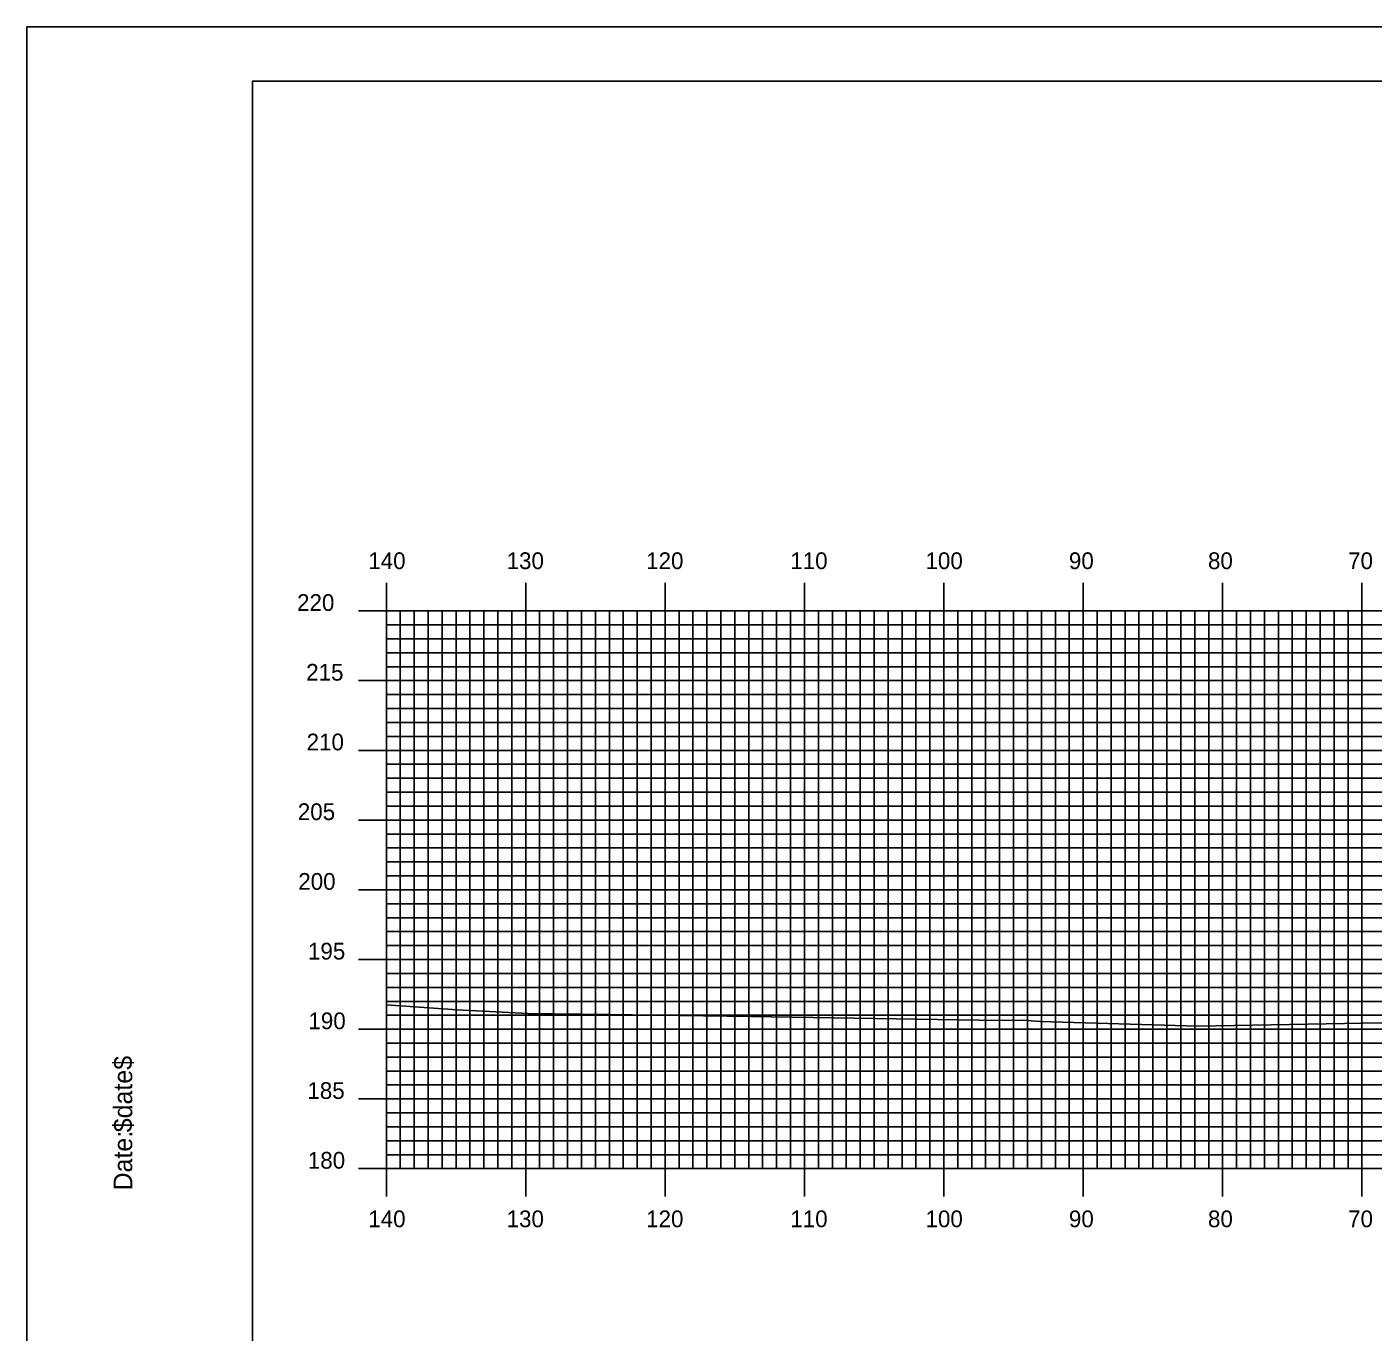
# Model space of a CAD drawing. Extents: x 1810587 to 1810930, y 442591 to 442811.
# Drawn here: x 1810586.6 to 1810683.2, y 442716.9 to 442810.5 of the extents above; entities that cross this region are included whole.
import ezdxf

# ---------------------------------------------------------------- set-up
doc = ezdxf.new("R2010")
doc.units = 0
for name, color, linetype in [('BORDER', 7, 'Continuous'), ('H_V ANNOTATION', 7, 'Continuous'), ('MAJOR', 7, 'Continuous'), ('MINOR', 7, 'Continuous'), ('PLOT BOUNDARY', 7, 'Continuous'), ('S_Roadway_Centerline', 7, 'Continuous')]:
    doc.layers.add(name, color=color, linetype=linetype)

msp = doc.modelspace()

# ---------------------------------------------------------------- linework, layer by layer
at = {"layer": 'BORDER'}
msp.add_lwpolyline([(1810602.777, 442596.665), (1810922.777, 442596.665), (1810922.777, 442806.665), (1810602.777, 442806.665)], close=True, dxfattribs=at)
at = {"layer": 'MAJOR'}
for p, q in [((1810612.377, 442770.669), (1810612.377, 442768.665)), ((1810622.377, 442770.669), (1810622.377, 442768.665)), ((1810632.377, 442770.669), (1810632.377, 442768.665)), ((1810642.377, 442770.669), (1810642.377, 442768.665)), ((1810652.377, 442770.669), (1810652.377, 442768.665)), ((1810662.377, 442770.669), (1810662.377, 442768.665)), ((1810672.377, 442770.669), (1810672.377, 442768.665)), ((1810682.377, 442770.669), (1810682.377, 442768.665)), ((1810610.373, 442768.665), (1810612.377, 442768.665)), ((1810612.377, 442768.665), (1810892.377, 442768.665)), ((1810612.377, 442728.665), (1810612.377, 442768.665)), ((1810612.377, 442728.665), (1810612.377, 442768.665)), ((1810612.377, 442768.665), (1810892.377, 442768.665)), ((1810622.377, 442728.665), (1810622.377, 442768.665)), ((1810632.377, 442728.665), (1810632.377, 442768.665)), ((1810642.377, 442728.665), (1810642.377, 442768.665)), ((1810652.377, 442728.665), (1810652.377, 442768.665)), ((1810662.377, 442728.665), (1810662.377, 442768.665)), ((1810672.377, 442728.665), (1810672.377, 442768.665)), ((1810682.377, 442728.665), (1810682.377, 442768.665)), ((1810610.373, 442763.665), (1810612.377, 442763.665)), ((1810612.377, 442763.665), (1810892.377, 442763.665)), ((1810610.373, 442758.665), (1810612.377, 442758.665)), ((1810612.377, 442758.665), (1810892.377, 442758.665)), ((1810610.373, 442753.665), (1810612.377, 442753.665)), ((1810612.377, 442753.665), (1810892.377, 442753.665)), ((1810610.373, 442748.665), (1810612.377, 442748.665)), ((1810612.377, 442748.665), (1810892.377, 442748.665)), ((1810610.373, 442743.665), (1810612.377, 442743.665)), ((1810612.377, 442743.665), (1810892.377, 442743.665)), ((1810610.373, 442738.665), (1810612.377, 442738.665)), ((1810612.377, 442738.665), (1810892.377, 442738.665)), ((1810610.373, 442733.665), (1810612.377, 442733.665)), ((1810612.377, 442733.665), (1810892.377, 442733.665)), ((1810610.373, 442728.665), (1810612.377, 442728.665)), ((1810612.377, 442728.665), (1810892.377, 442728.665)), ((1810612.377, 442728.665), (1810892.377, 442728.665)), ((1810612.377, 442726.661), (1810612.377, 442728.665)), ((1810622.377, 442726.661), (1810622.377, 442728.665)), ((1810632.377, 442726.661), (1810632.377, 442728.665)), ((1810642.377, 442726.661), (1810642.377, 442728.665)), ((1810652.377, 442726.661), (1810652.377, 442728.665)), ((1810662.377, 442726.661), (1810662.377, 442728.665)), ((1810672.377, 442726.661), (1810672.377, 442728.665)), ((1810682.377, 442726.661), (1810682.377, 442728.665))]:
    msp.add_line(p, q, dxfattribs=at)
at = {"layer": 'MINOR'}
for p, q in [((1810613.377, 442728.665), (1810613.377, 442768.665)), ((1810614.377, 442728.665), (1810614.377, 442768.665)), ((1810615.377, 442728.665), (1810615.377, 442768.665)), ((1810616.377, 442728.665), (1810616.377, 442768.665)), ((1810617.377, 442728.665), (1810617.377, 442768.665)), ((1810618.377, 442728.665), (1810618.377, 442768.665)), ((1810619.377, 442728.665), (1810619.377, 442768.665)), ((1810620.377, 442728.665), (1810620.377, 442768.665)), ((1810621.377, 442728.665), (1810621.377, 442768.665)), ((1810623.377, 442728.665), (1810623.377, 442768.665)), ((1810624.377, 442728.665), (1810624.377, 442768.665)), ((1810625.377, 442728.665), (1810625.377, 442768.665)), ((1810626.377, 442728.665), (1810626.377, 442768.665)), ((1810627.377, 442728.665), (1810627.377, 442768.665)), ((1810628.377, 442728.665), (1810628.377, 442768.665)), ((1810629.377, 442728.665), (1810629.377, 442768.665)), ((1810630.377, 442728.665), (1810630.377, 442768.665)), ((1810631.377, 442728.665), (1810631.377, 442768.665)), ((1810633.377, 442728.665), (1810633.377, 442768.665)), ((1810634.377, 442728.665), (1810634.377, 442768.665)), ((1810635.377, 442728.665), (1810635.377, 442768.665)), ((1810636.377, 442728.665), (1810636.377, 442768.665)), ((1810637.377, 442728.665), (1810637.377, 442768.665)), ((1810638.377, 442728.665), (1810638.377, 442768.665)), ((1810639.377, 442728.665), (1810639.377, 442768.665)), ((1810640.377, 442728.665), (1810640.377, 442768.665)), ((1810641.377, 442728.665), (1810641.377, 442768.665)), ((1810643.377, 442728.665), (1810643.377, 442768.665)), ((1810644.377, 442728.665), (1810644.377, 442768.665)), ((1810645.377, 442728.665), (1810645.377, 442768.665)), ((1810646.377, 442728.665), (1810646.377, 442768.665)), ((1810647.377, 442728.665), (1810647.377, 442768.665)), ((1810648.377, 442728.665), (1810648.377, 442768.665)), ((1810649.377, 442728.665), (1810649.377, 442768.665)), ((1810650.377, 442728.665), (1810650.377, 442768.665)), ((1810651.377, 442728.665), (1810651.377, 442768.665)), ((1810653.377, 442728.665), (1810653.377, 442768.665)), ((1810654.377, 442728.665), (1810654.377, 442768.665)), ((1810655.377, 442728.665), (1810655.377, 442768.665)), ((1810656.377, 442728.665), (1810656.377, 442768.665)), ((1810657.377, 442728.665), (1810657.377, 442768.665)), ((1810658.377, 442728.665), (1810658.377, 442768.665)), ((1810659.377, 442728.665), (1810659.377, 442768.665)), ((1810660.377, 442728.665), (1810660.377, 442768.665)), ((1810661.377, 442728.665), (1810661.377, 442768.665)), ((1810663.377, 442728.665), (1810663.377, 442768.665)), ((1810664.377, 442728.665), (1810664.377, 442768.665)), ((1810665.377, 442728.665), (1810665.377, 442768.665)), ((1810666.377, 442728.665), (1810666.377, 442768.665)), ((1810667.377, 442728.665), (1810667.377, 442768.665)), ((1810668.377, 442728.665), (1810668.377, 442768.665)), ((1810669.377, 442728.665), (1810669.377, 442768.665)), ((1810670.377, 442728.665), (1810670.377, 442768.665)), ((1810671.377, 442728.665), (1810671.377, 442768.665)), ((1810673.377, 442728.665), (1810673.377, 442768.665)), ((1810674.377, 442728.665), (1810674.377, 442768.665)), ((1810675.377, 442728.665), (1810675.377, 442768.665)), ((1810676.377, 442728.665), (1810676.377, 442768.665)), ((1810677.377, 442728.665), (1810677.377, 442768.665)), ((1810678.377, 442728.665), (1810678.377, 442768.665)), ((1810679.377, 442728.665), (1810679.377, 442768.665)), ((1810680.377, 442728.665), (1810680.377, 442768.665)), ((1810681.377, 442728.665), (1810681.377, 442768.665)), ((1810612.377, 442767.665), (1810892.377, 442767.665)), ((1810612.377, 442767.665), (1810614.381, 442767.665)), ((1810612.377, 442766.665), (1810892.377, 442766.665)), ((1810612.377, 442766.665), (1810614.381, 442766.665)), ((1810612.377, 442765.665), (1810892.377, 442765.665)), ((1810612.377, 442765.665), (1810614.381, 442765.665)), ((1810612.377, 442764.665), (1810892.377, 442764.665)), ((1810612.377, 442764.665), (1810614.381, 442764.665)), ((1810612.377, 442762.665), (1810892.377, 442762.665)), ((1810612.377, 442762.665), (1810614.381, 442762.665)), ((1810612.377, 442761.665), (1810892.377, 442761.665)), ((1810612.377, 442761.665), (1810614.381, 442761.665)), ((1810612.377, 442760.665), (1810892.377, 442760.665)), ((1810612.377, 442760.665), (1810614.381, 442760.665)), ((1810612.377, 442759.665), (1810892.377, 442759.665)), ((1810612.377, 442759.665), (1810614.381, 442759.665)), ((1810612.377, 442757.665), (1810892.377, 442757.665)), ((1810612.377, 442757.665), (1810614.381, 442757.665)), ((1810612.377, 442756.665), (1810892.377, 442756.665)), ((1810612.377, 442756.665), (1810614.381, 442756.665)), ((1810612.377, 442755.665), (1810892.377, 442755.665)), ((1810612.377, 442755.665), (1810614.381, 442755.665)), ((1810612.377, 442754.665), (1810892.377, 442754.665)), ((1810612.377, 442754.665), (1810614.381, 442754.665)), ((1810612.377, 442752.665), (1810892.377, 442752.665)), ((1810612.377, 442752.665), (1810614.381, 442752.665)), ((1810612.377, 442751.665), (1810892.377, 442751.665)), ((1810612.377, 442751.665), (1810614.381, 442751.665)), ((1810612.377, 442750.665), (1810892.377, 442750.665)), ((1810612.377, 442750.665), (1810614.381, 442750.665)), ((1810612.377, 442749.665), (1810892.377, 442749.665)), ((1810612.377, 442749.665), (1810614.381, 442749.665)), ((1810612.377, 442747.665), (1810892.377, 442747.665)), ((1810612.377, 442747.665), (1810614.381, 442747.665)), ((1810612.377, 442746.665), (1810892.377, 442746.665)), ((1810612.377, 442746.665), (1810614.381, 442746.665)), ((1810612.377, 442745.665), (1810892.377, 442745.665)), ((1810612.377, 442745.665), (1810614.381, 442745.665)), ((1810612.377, 442744.665), (1810892.377, 442744.665)), ((1810612.377, 442744.665), (1810614.381, 442744.665)), ((1810612.377, 442742.665), (1810892.377, 442742.665)), ((1810612.377, 442742.665), (1810614.381, 442742.665)), ((1810612.377, 442741.665), (1810892.377, 442741.665)), ((1810612.377, 442741.665), (1810614.381, 442741.665)), ((1810612.377, 442740.665), (1810892.377, 442740.665)), ((1810612.377, 442740.665), (1810614.381, 442740.665)), ((1810612.377, 442739.665), (1810892.377, 442739.665)), ((1810612.377, 442739.665), (1810614.381, 442739.665)), ((1810612.377, 442737.665), (1810892.377, 442737.665)), ((1810612.377, 442737.665), (1810614.381, 442737.665)), ((1810612.377, 442736.665), (1810892.377, 442736.665)), ((1810612.377, 442736.665), (1810614.381, 442736.665)), ((1810612.377, 442735.665), (1810892.377, 442735.665)), ((1810612.377, 442735.665), (1810614.381, 442735.665)), ((1810612.377, 442734.665), (1810892.377, 442734.665)), ((1810612.377, 442734.665), (1810614.381, 442734.665)), ((1810612.377, 442732.665), (1810892.377, 442732.665)), ((1810612.377, 442732.665), (1810614.381, 442732.665)), ((1810612.377, 442731.665), (1810892.377, 442731.665)), ((1810612.377, 442731.665), (1810614.381, 442731.665)), ((1810612.377, 442730.665), (1810892.377, 442730.665)), ((1810612.377, 442730.665), (1810614.381, 442730.665)), ((1810612.377, 442729.665), (1810892.377, 442729.665)), ((1810612.377, 442729.665), (1810614.381, 442729.665))]:
    msp.add_line(p, q, dxfattribs=at)
at = {"layer": 'PLOT BOUNDARY'}
msp.add_lwpolyline([(1810586.59, 442590.547), (1810926.59, 442590.547), (1810926.59, 442810.547), (1810586.59, 442810.547)], close=True, dxfattribs=at)
at = {"layer": 'S_Roadway_Centerline'}
msp.add_lwpolyline([(1810612.377, 442740.403), (1810617.462, 442740.055), (1810622.558, 442739.785), (1810628.316, 442739.724), (1810638.526, 442739.577), (1810656.386, 442739.297), (1810658.007, 442739.312), (1810659.285, 442739.228), (1810670.597, 442738.88), (1810683.757, 442739.125), (1810700.479, 442738.664), (1810710.156, 442738.284), (1810720.854, 442738.411), (1810737.474, 442738.884), (1810739.437, 442738.87), (1810741.277, 442738.823), (1810752.122, 442738.14), (1810762.757, 442738.223), (1810764.361, 442738.195), (1810782.794, 442738.075)], dxfattribs=at)

# ---------------------------------------------------------------- texts
at = {"layer": 'BORDER'}
for s, p in [('$date$', (1810594.146, 442731.275)), ('Date:', (1810594.146, 442727.099))]:
    msp.add_text(s, height=1.3392, rotation=90, dxfattribs=at).set_placement(p)
at = {"layer": 'H_V ANNOTATION'}
for s, p in [('140', (1810611.081, 442771.665)), ('130', (1810621.006, 442771.665)), ('120', (1810631.017, 442771.665)), ('110', (1810641.36, 442771.665)), ('100', (1810651.06, 442771.665)), ('90', (1810661.349, 442771.665)), ('80', (1810671.327, 442771.665)), ('70', (1810681.381, 442771.665)), ('220', (1810605.972, 442768.665)), ('215', (1810606.626, 442763.665)), ('210', (1810606.658, 442758.665)), ('205', (1810606.026, 442753.665)), ('200', (1810606.058, 442748.665)), ('195', (1810606.754, 442743.665)), ('190', (1810606.786, 442738.665)), ('185', (1810606.711, 442733.665)), ('180', (1810606.743, 442728.665)), ('140', (1810611.081, 442724.465)), ('130', (1810621.006, 442724.465)), ('120', (1810631.017, 442724.465)), ('110', (1810641.36, 442724.465)), ('100', (1810651.06, 442724.465)), ('90', (1810661.349, 442724.465)), ('80', (1810671.327, 442724.465)), ('70', (1810681.381, 442724.465))]:
    msp.add_text(s, height=1.2, dxfattribs=at).set_placement(p)
at = {"layer": 'MAJOR'}
msp.add_text('-', height=0.012, dxfattribs=at).set_placement((1810612.368, 442728.665))

doc.saveas('drawing.dxf')
